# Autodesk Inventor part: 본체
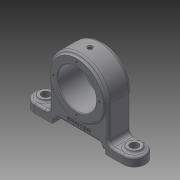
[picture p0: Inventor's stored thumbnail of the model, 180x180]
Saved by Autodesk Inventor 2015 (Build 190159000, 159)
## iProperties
Created: 2019-05
Part Number: 본체
Material: 알루미늄 6061
Document SubType Name: Modeling
Designer: now
Density: 2.7 g/cm^3
Appearance: 기본값
Mass: 456.09 g
Surface Area: 318.797 cm^2
Volume: 168.922 cm^3
Author: now
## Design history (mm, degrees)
sketch "스케치1"
  geometry: L1 (-60, -15)-(60, -15); L2 (60, -15)-(60, 15); L3 (60, 15)-(-60, 15); L4 (-60, 15)-(-60, -15); L5 (-60, -15)-(60, 15); L6 (60, -15)-(-60, 15); 1 further point
  constraints: 12 end point, 2 midpoint, 2 parallel, 1 horizontal, 1 perpendicular
  dimensions: "d0" = 120 distance of L2.end L3.end; "d1" = 30 distance of L1.end L2.end
extrude "돌출1" new body sketch "스케치1" distance "d2" = 12; taper "d3" = 0 deg
sketch "스케치2"
  geometry: L1 (60, -15)-(60, 15) reference; L2 (-60, 15)-(-60, -15) reference; 3 further points
  constraints: 2 midpoint, 2 vertical alignment, 4 other
extrude "돌출2" join sketch "스케치2" distance "d4" = 12; taper "d5" = 0 deg
sketch "스케치3"
  geometry: C1 r 9 at (-60, 0); C2 r 9 at (60, 0); A1 r 15 centre (60, 0) between (60, -15) and (60, 15) reference; A2 r 15 centre (-60, 0) between (-60, 15) and (-60, -15) reference; 1 further point
  constraints: 2 centre point, 2 coincident
  dimensions: "d6" = 18 diameter of C2; "d7" = 18 diameter of C1
extrude "돌출3" join sketch "스케치3" distance "d8" = 3; taper "d9" = 0 deg
sketch "스케치4"
  geometry: C1 r 9 at (0, 0) reference; 1 further point
hole "구멍1" sketch "스케치4" at (0, 0) diameter "d10" = 11; stored, may be unused: countersink angle "d14" = 90 deg, drill point angle "d16" = 118 deg; dims "d11" = 6, "d12" = 4, "d13" = 2, "d15" = 8
sketch "스케치5"
  geometry: L1 (-51, 15)-(-51, 12) reference; L2 (-51, 12)-(51, 12) reference; L3 (51, 12)-(51, 15) reference; L4 (51, 15)-(54.5, 15) reference; L5 (54.5, 15)-(54.5, 0) reference; L6 (54.5, 0)-(-54.5, 0) reference; L7 (-54.5, 0)-(-54.5, 15) reference; L8 (-54.5, 15)-(-51, 15) reference; L9 (75, 12)-(75, 0) reference; L10 (75, 0)-(65.5, 0) reference; L11 (65.5, 0)-(65.5, 15) reference; L12 (65.5, 15)-(69, 15) reference; L13 (69, 15)-(69, 12) reference; L14 (69, 12)-(75, 12) reference; L15 (-75, 0)-(-75, 12) reference; L16 (-75, 12)-(-69, 12) reference; L17 (-69, 12)-(-69, 15) reference; L18 (-69, 15)-(-65.5, 15) reference; L19 (-65.5, 15)-(-65.5, 0) reference; L20 (-65.5, 0)-(-75, 0) reference; L21 (40, 60)-(40, 12); L22 (-40, 60)-(-40, 12); A1 r 40 centre (0, 60) between (40, 60) and (-40, 60); 2 further points
  constraints: 4 end point, 2 point on circle, 2 point on line, 2 tangent, 2 vertical, 1 centre point, 1 midpoint, 1 vertical alignment
  dimensions: "d17" = 80 diameter of A1; "d18" = 60 distance of A1.centre point (0, 0)
extrude "돌출4" join sketch "스케치5" stored distance "d19" = 30; taper "d20" = 0 deg
sketch "스케치6"
  geometry: L1 (0, 0)-(120, 0) reference; L2 (24, 4)-(96, 4); L3 (96, 4)-(96, 0); L4 (96, 0)-(24, 0); L5 (24, 0)-(24, 4); 2 further points
  constraints: 8 end point, 2 midpoint, 2 parallel, 1 horizontal, 1 perpendicular, 1 point on line
  dimensions: "d21" = 4 distance of L2.end L3.end; "d24" = 72 distance between parallel lines of L5 L3
extrude "돌출5" cut sketch "스케치6" stored distance "d25" = 36; taper "d26" = 0 deg
sketch "스케치7"
  geometry: L1 (-96, 4)-(-24, 4) reference; L2 (-90, 10)-(-30, 10); L3 (-30, 10)-(-30, 4); L4 (-30, 4)-(-90, 4); L5 (-90, 4)-(-90, 10); 2 further points
  constraints: 8 end point, 2 midpoint, 2 parallel, 1 horizontal, 1 perpendicular
  dimensions: "d27" = 60 distance of L3.end L4.end; "d28" = 6 distance of L2.end L3.end
extrude "돌출6" cut sketch "스케치7" stored distance "d29" = 36; taper "d30" = 0 deg
sketch "스케치8"
  geometry: A1 r 40 centre (0, 60) between (40, 60) and (-40, 60) reference; 1 further point
hole "구멍2" sketch "스케치8" at (0, 60) diameter "d31" = 52; stored, may be unused: countersink angle "d35" = 90 deg, drill point angle "d37" = 118 deg; dims "d32" = 6, "d33" = 4, "d34" = 2, "d36" = 8
sketch "스케치10"
  geometry: C1 r 26 at (-60, 60) reference; C2 r 36 at (-60, 60); A1 r 40 centre (-60, 60) between (-20, 60) and (-100, 60) reference; 1 further point
  constraints: 1 centre point, 1 coincident
  dimensions: "d38" = 72 diameter of C2
extrude "돌출7" join sketch "스케치10" distance "d39" = 3; taper "d40" = 0 deg
node "작업 평면1"
sketch "스케치11"
  geometry: 1 further point
hole "구멍3" sketch "스케치11" at (0, 0) diameter "d42" = 4.917; stored, may be unused: countersink angle "d46" = 90 deg, drill point angle "d48" = 118 deg; dims "d43" = 8, "d44" = 7, "d45" = 1, "d47" = 10
sketch "스케치12"
  geometry: C1 r 26 at (0, 0) reference; 2 further points
  constraints: 1 vertical alignment
  dimensions: "d49" = 31 distance of point (0, 31) C1.centre
hole "구멍4" sketch "스케치12" at (0, 31) diameter "d50" = 3.242; stored, may be unused: countersink angle "d54" = 90 deg, drill point angle "d56" = 118 deg; dims "d51" = 6, "d52" = 7, "d53" = 1, "d55" = 8
fillet "모깎기1" dims "d60" = 3
sketch "스케치13"
  geometry: C1 r 1.5 at (0, 26); 2 further points
  constraints: 2 vertical alignment, 1 centre point, 1 other
  dimensions: "d61" = 3 diameter of C1
extrude "돌출8" cut sketch "스케치13" stored distance "d62" = 3; taper "d63" = 0 deg
sketch "스케치15"
  geometry: L1 (30, 10)-(90, 10) reference; 2 further points
  constraints: 1 vertical alignment, 1 other
  dimensions: "d73" = 7 distance from line of L1 point (60, 17)
feature "엠보싱1" sketch "스케치15" dims "d74" = 0.5, "d75" = 0
fillet "모깎기9" dims "d76" = 3
fillet "모깎기2" dims "d64" = 6
fillet "모깎기3" dims "d65" = 3
fillet "모깎기4" dims "d66" = 3
fillet "모깎기5" dims "d67" = 3
fillet "모깎기6" dims "d68" = 3
fillet "모깎기7" dims "d69" = 3
fillet "모깎기8" dims "d70" = 1
node "작업 평면2"
sketch "스케치16"
  geometry: 1 further point
hole "구멍5" sketch "스케치16" at (0, 0) diameter "d78" = 2; stored, may be unused: countersink angle "d82" = 90 deg, drill point angle "d84" = 118 deg; dims "d79" = 6, "d80" = 7, "d81" = 1, "d83" = 8
fillet "모깎기10" dims "d85" = 3
node "솔리드1"
mirror "대칭1"
mirror "대칭2"
pattern_circular "원형 패턴1" dims angle "d58" = 360 deg
mirror "대칭3"
node "절단 모서리 투영1"
